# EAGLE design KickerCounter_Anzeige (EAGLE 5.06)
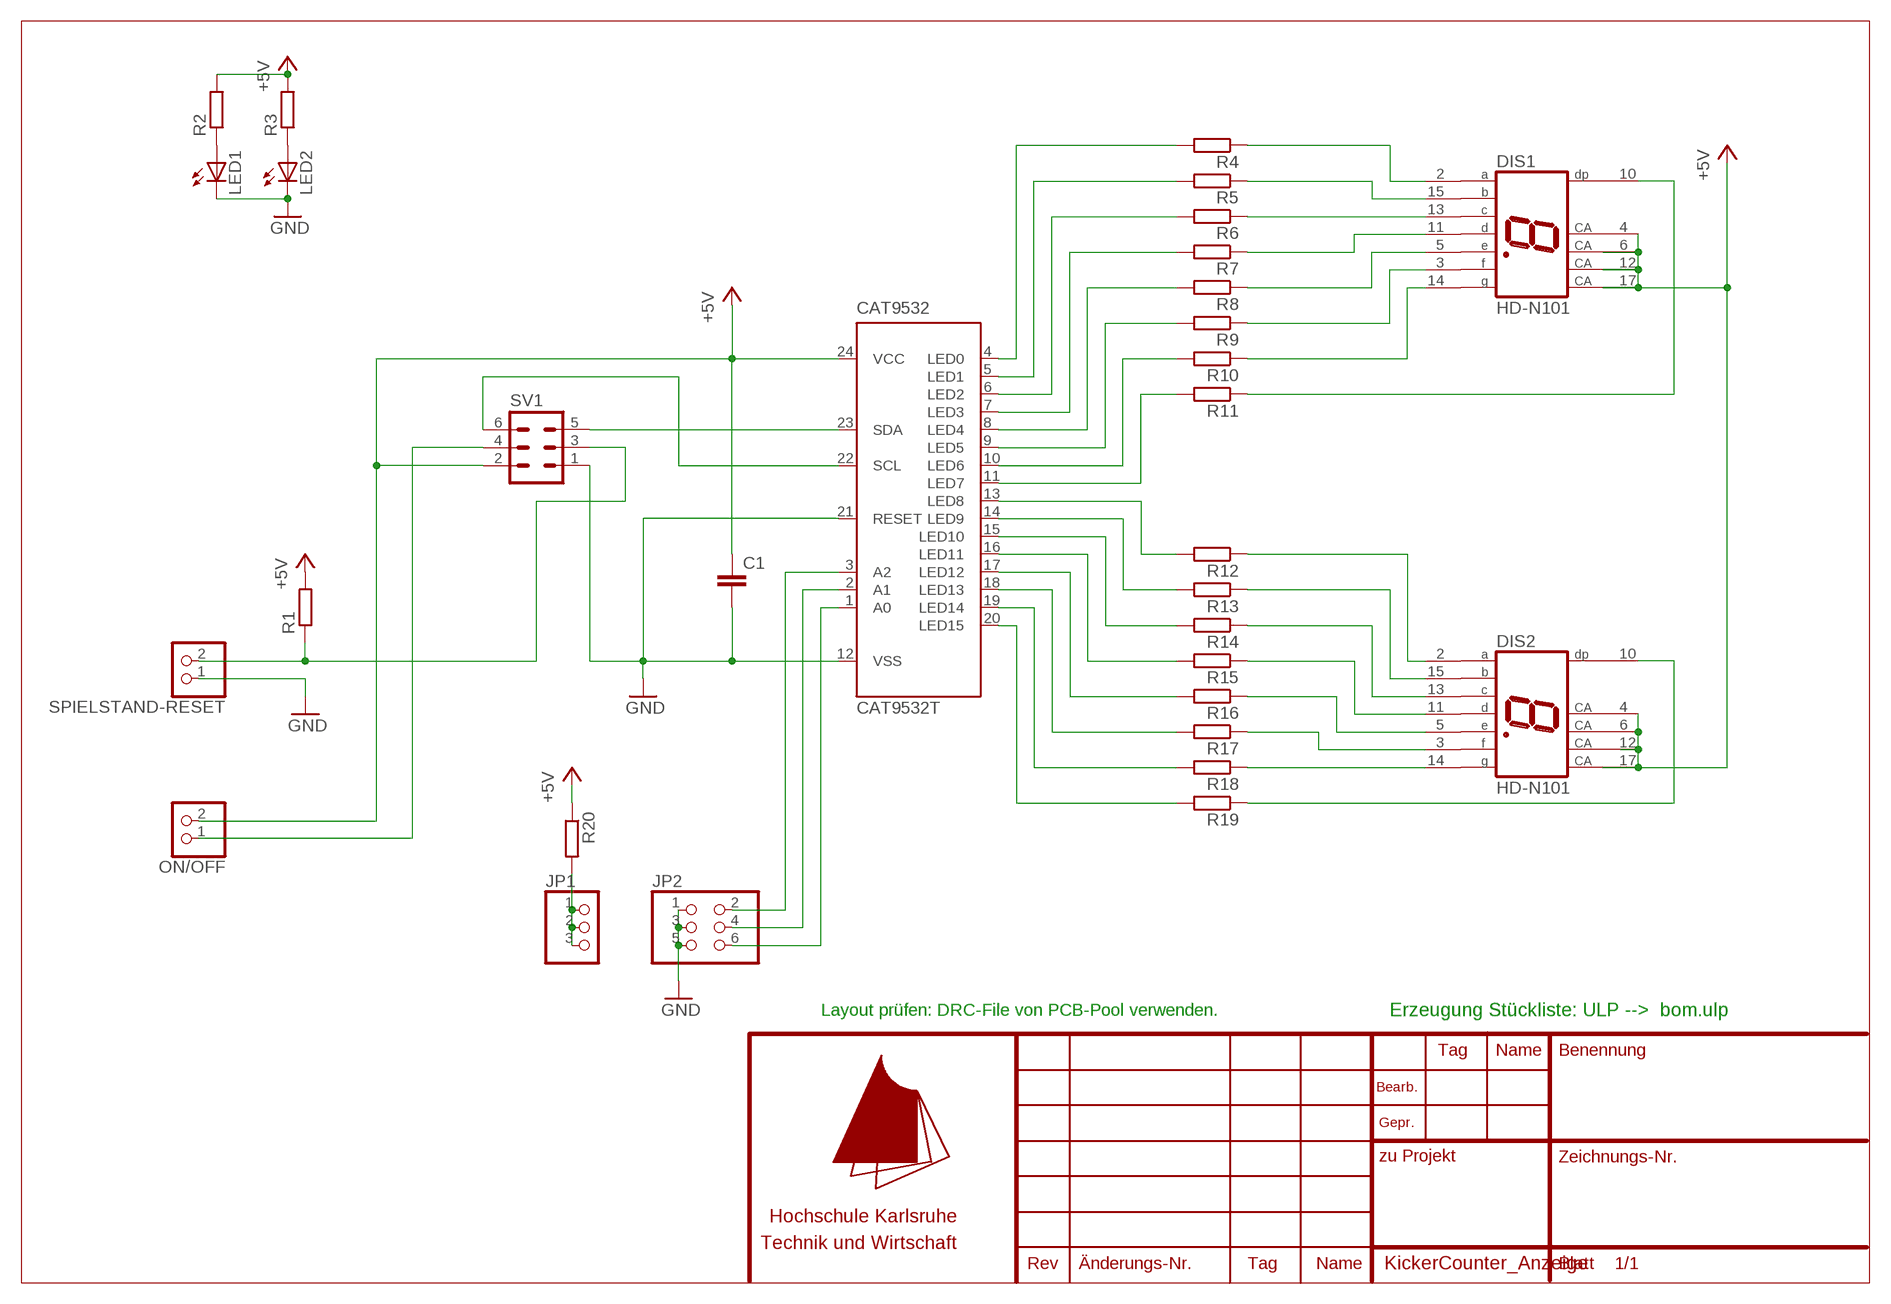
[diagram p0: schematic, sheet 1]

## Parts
C1  C-EUC1206  [C1206]
DIS1  HD-N101  [HDSP-Q]
DIS2  HD-N101  [HDSP-Q]
IC1  CAT9532T  [SO24]
JP1  PINHD-1X3  [1X03]
JP2  PINHD-2X3  [2X03]
LED1  LED3MM  [LED3MM]
LED2  LED3MM  [LED3MM]
ON/OFF  PINHD-1X2  [1X02]
R1  R-EU_R1206  [R1206]
R2  R-EU_R1206  [R1206]
R3  R-EU_R1206  [R1206]
R4  R-EU_R1206  [R1206]
R5  R-EU_R1206  [R1206]
R6  R-EU_R1206  [R1206]
R7  R-EU_R1206  [R1206]
R8  R-EU_R1206  [R1206]
R9  R-EU_R1206  [R1206]
R10  R-EU_R1206  [R1206]
R11  R-EU_R1206  [R1206]
R12  R-EU_R1206  [R1206]
R13  R-EU_R1206  [R1206]
R14  R-EU_R1206  [R1206]
R15  R-EU_R1206  [R1206]
R16  R-EU_R1206  [R1206]
R17  R-EU_R1206  [R1206]
R18  R-EU_R1206  [R1206]
R19  R-EU_R1206  [R1206]
R20  R-EU_R1206  [R1206]
SPIELSTAND-RESET  PINHD-1X2  [1X02]
SV1  ML6  [ML6]

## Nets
+5V: C1.1 DIS1.4(CA) DIS1.6(CA) DIS1.12(CA) DIS1.17(CA) DIS2.4(CA) DIS2.6(CA) DIS2.12(CA) DIS2.17(CA) IC1.24(VCC) ON/OFF.2 R1.2 R2.2 R3.2 R20.1 SV1.2
GND: C1.2 IC1.12(VSS) IC1.21(RESET) JP2.1 JP2.3 JP2.5 LED1.K(C) LED2.K(C) SPIELSTAND-RESET.1 SV1.1
N$1: IC1.1(A0) JP2.6
N$2: IC1.2(A1) JP2.4
N$3: IC1.3(A2) JP2.2
N$4: IC1.4(LED0) R4.2
N$5: IC1.5(LED1) R5.2
N$6: IC1.6(LED2) R6.2
N$7: IC1.7(LED3) R7.2
N$8: IC1.8(LED4) R8.2
N$9: IC1.9(LED5) R9.2
N$10: IC1.10(LED6) R10.2
N$11: IC1.11(LED7) R11.2
N$12: DIS1.2(A) R4.1
N$13: DIS1.15(B) R5.1
N$14: DIS1.3(F) R9.1
N$15: DIS1.14(G) R10.1
N$16: DIS1.5(E) R8.1
N$17: DIS1.11(D) R7.1
N$18: DIS1.13(C) R6.1
N$19: DIS1.10(DP) R11.1
N$20: LED1.A R2.1
N$21: IC1.23(SDA) SV1.5
N$22: IC1.22(SCL) SV1.6
N$23: LED2.A R3.1
N$24: ON/OFF.1 SV1.4
N$25: R1.1 SPIELSTAND-RESET.2 SV1.3
N$26: IC1.13(LED8) R12.2
N$27: IC1.14(LED9) R13.2
N$28: IC1.15(LED10) R14.2
N$29: IC1.16(LED11) R15.2
N$30: IC1.17(LED12) R16.2
N$31: IC1.18(LED13) R17.2
N$32: IC1.19(LED14) R18.2
N$33: IC1.20(LED15) R19.2
N$34: DIS2.2(A) R12.1
N$35: DIS2.15(B) R13.1
N$36: DIS2.13(C) R14.1
N$37: DIS2.11(D) R15.1
N$38: DIS2.5(E) R16.1
N$39: DIS2.3(F) R17.1
N$40: DIS2.14(G) R18.1
N$41: DIS2.10(DP) R19.1
N$42: JP1.1 JP1.2 JP1.3 R20.2

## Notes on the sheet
- Layout prüfen: DRC-File von PCB-Pool verwenden. | Erzeugung Stückliste: ULP -->  bom.ulp

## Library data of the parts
C1 = rcl:C-EU: CAPACITOR, European symbol
DIS1 DIS2 = display-hp:HD-N101: LED DISPLAY 1-character 7 segment, decimal point right
IC1 = CAT9532:CAT9532: I2C-Bus 4-digit LED-DRIVER
JP1 = pinhead:PINHD-1X3: PIN HEADER
JP2 = pinhead:PINHD-2X3: PIN HEADER
LED1 LED2 = led:LED: LED
ON/OFF SPIELSTAND-RESET = pinhead:PINHD-1X2: PIN HEADER
R1-R20 = rcl:R-EU_: RESISTOR, European symbol
SV1 = con-ml:ML6: HARTING

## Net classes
0 default: width 0.152 mm, drill 0.305 mm, clearance 0.4 mm
1 5V: width 0.305 mm, drill 0.305 mm, clearance 0.4 mm
2 3V3: width 0.305 mm, drill 0.305 mm, clearance 0.4 mm

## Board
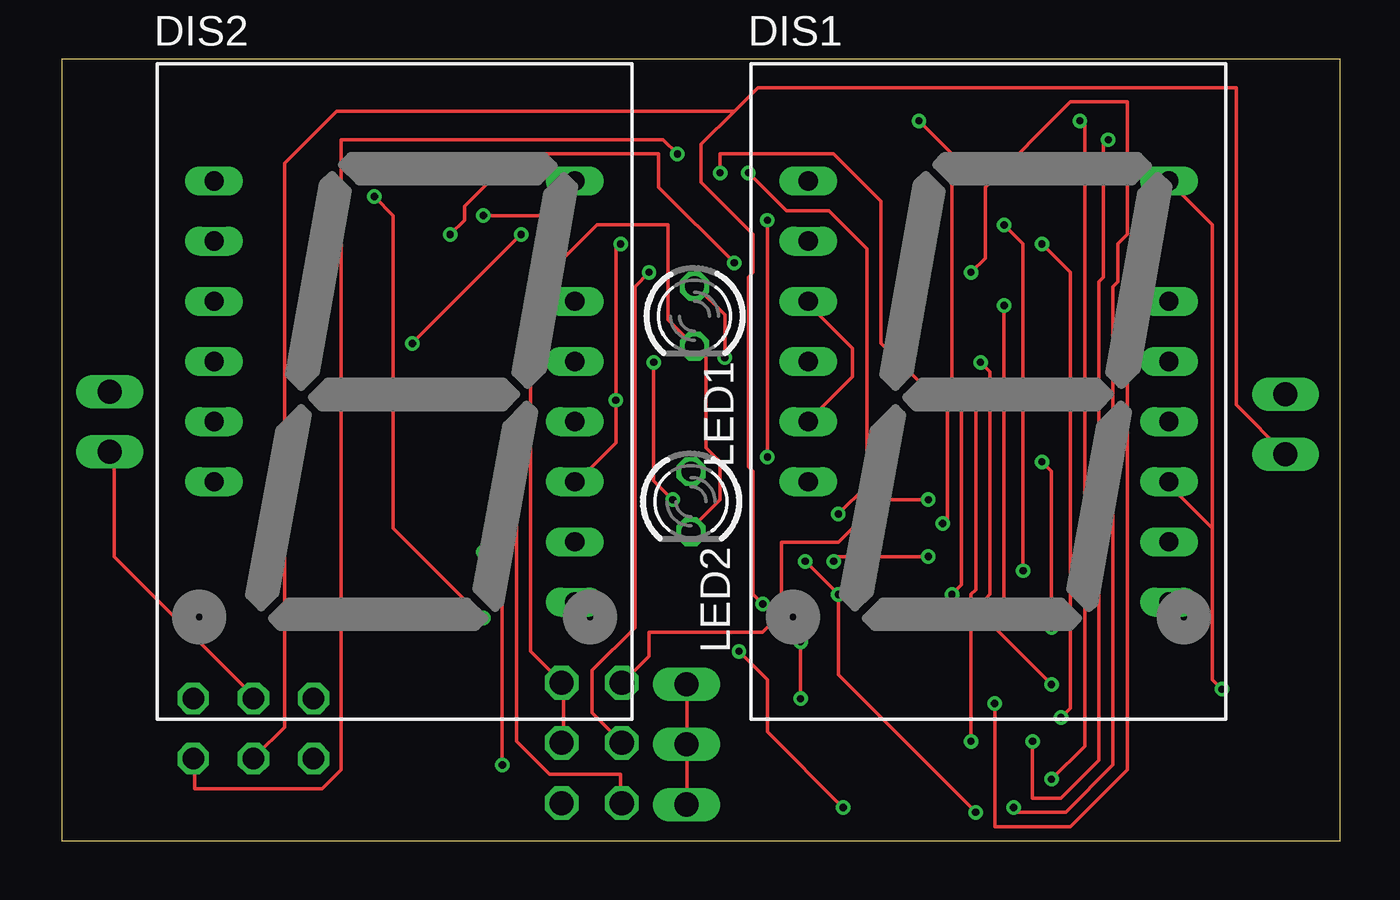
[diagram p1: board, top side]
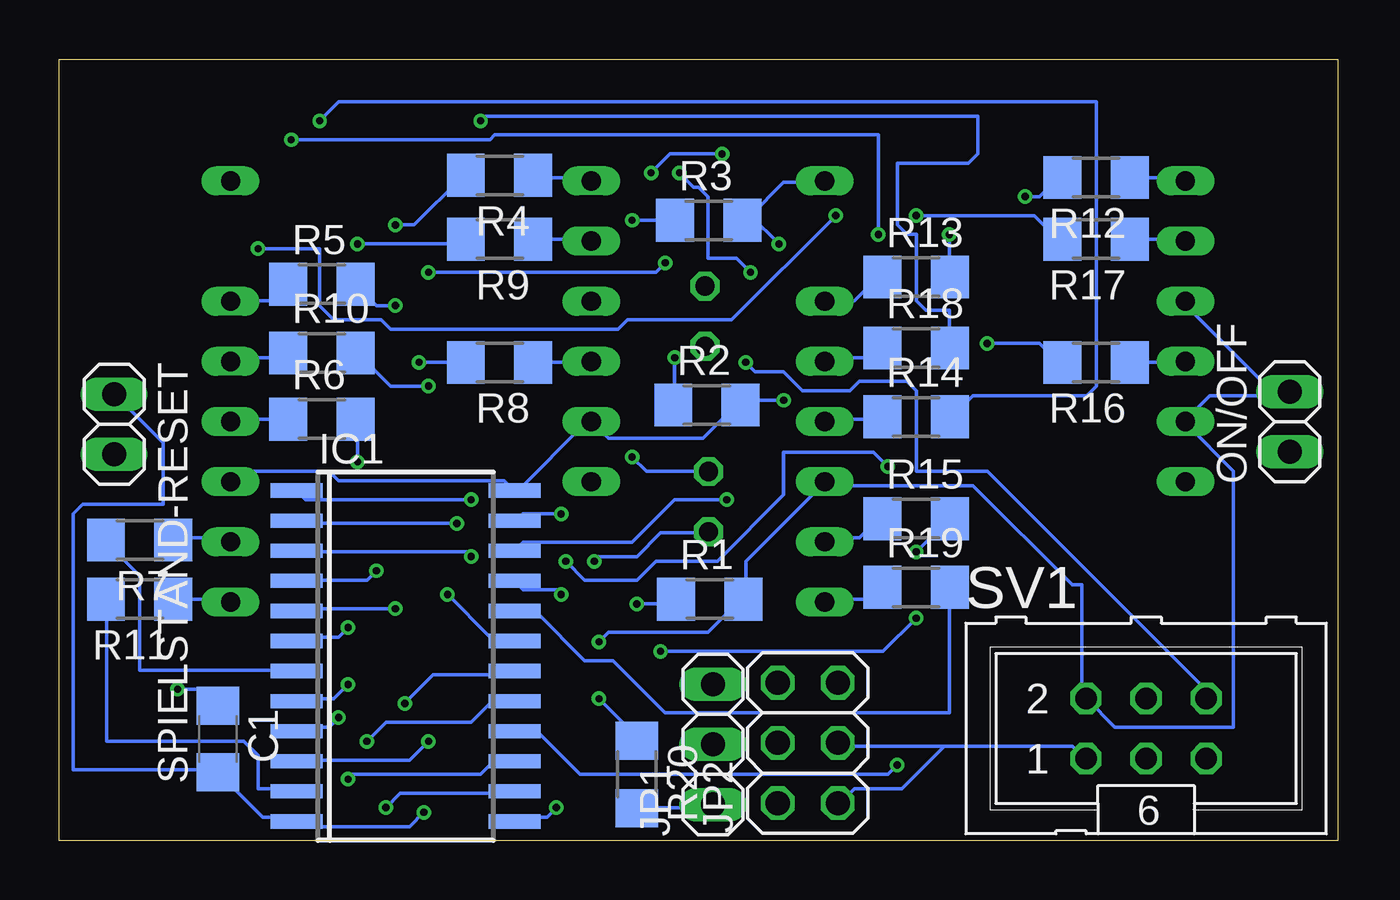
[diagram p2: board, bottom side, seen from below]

Size 54 x 33 mm. Coordinates in mm from the lower left corner, seen from the top.
Outline: 0,0 54,0 54,33 0,33 0,0
Copper layers (1*16): Top 0.035mm / dielectric 1.5mm / Bottom 0.035mm
Design rules "PCB-POOL": minimum track width 6mil, minimum drill 12mil, track to track 6mil, track to pad 6mil, pad to pad 6mil, via to via 6mil, smd to smd 6mil, copper to edge 20mil, drill to drill 8mil, minimum pad ring 8mil, minimum via ring 6mil, stop-mask expansion 3mil, vias tented up to drill 0mil, thermal gap 8mil

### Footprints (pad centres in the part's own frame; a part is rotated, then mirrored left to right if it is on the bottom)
C1206 = smd 1.6 x 1.8: 1 -1.4,0; 2 1.4,0
HDSP-Q = drill 0.813 long: 2 -7.62,8.89; 3 -7.62,6.35; 4 -7.62,3.81; 5 -7.62,1.27; 6 -7.62,-1.27; 7 -7.62,-3.81; 10 7.62,-8.89; 11 7.62,-6.35; 12 7.62,-3.81; 13 7.62,-1.27; 14 7.62,1.27; 15 7.62,3.81; 17 7.62,8.89
SO24 = smd 0.6 x 2.2: 1 -6.985,-4.6; 2 -5.715,-4.6; 3 -4.445,-4.6; 4 -3.175,-4.6; 5 -1.905,-4.6; 6 -0.635,-4.6; 7 0.635,-4.6; 8 1.905,-4.6; 9 3.175,-4.6; 10 4.445,-4.6; 11 5.715,-4.6; 12 6.985,-4.6; 13 6.985,4.6; 14 5.715,4.6; 15 4.445,4.6; 16 3.175,4.6; 17 1.905,4.6; 18 0.635,4.6; 19 -0.635,4.6; 20 -1.905,4.6; 21 -3.175,4.6; 22 -4.445,4.6; 23 -5.715,4.6; 24 -6.985,4.6
1X03 = drill 1.016 long: 1 -2.54,0; 2 0,0; 3 2.54,0
2X03 = drill 1.016 octagon: 1 -2.54,-1.27; 2 -2.54,1.27; 3 0,-1.27; 4 0,1.27; 5 2.54,-1.27; 6 2.54,1.27
LED3MM = drill 0.813 octagon: A -1.27,0; K 1.27,0
1X02 = drill 1.016 long: 1 -1.27,0; 2 1.27,0
R1206 = smd 1.6 x 1.803: 1 -1.422,0; 2 1.422,0
ML6 = drill 0.914 octagon: 1 -2.54,-1.27; 2 -2.54,1.27; 3 0,-1.27; 4 0,1.27; 5 2.54,-1.27; 6 2.54,1.27

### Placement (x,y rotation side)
C1  47.3,4.3 270 bottom
DIS1  39.14,18.97 0 top
DIS2  14.05,18.97 0 top
IC1  39.37,7.8 270 bottom
JP1  26.38,4.07 90 bottom
JP2  22.38,4.13 90 bottom
LED1  26.72,22.15 270 top
LED2  26.57,14.32 270 top
ON/OFF  2.02,17.69 90 bottom
R1  26.52,10.2 0 bottom
R2  26.64,18.4 0 bottom
R3  26.56,26.2 0 bottom
R4  35.4,28.1 180 bottom
R5  42.9,23.5 0 bottom
R6  42.9,17.8 0 bottom
R7  50.6,12.7 180 bottom
R8  35.4,20.2 180 bottom
R9  35.4,25.4 180 bottom
R10  42.9,20.6 0 bottom
R11  50.6,10.2 180 bottom
R12  10.2,28 180 bottom
R13  17.8,23.8 0 bottom
R14  17.8,17.9 0 bottom
R15  17.8,13.6 0 bottom
R16  10.2,20.2 180 bottom
R17  10.2,25.4 180 bottom
R18  17.8,20.8 0 bottom
R19  17.8,10.7 0 bottom
R20  29.6,2.8 270 bottom
SPIELSTAND-RESET  51.68,17.59 270 bottom
SV1  8.09,4.74 0 bottom

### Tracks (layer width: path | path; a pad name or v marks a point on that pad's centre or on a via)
+5V  (via drill 0.3)
  Top 0.152: DIS1.4 31.6,22.6 33.4,20.8 33.4,19.6 31.6,17.8 DIS1.6 | v49,6.4 48.6,6.8 48.6,13.2 | 48.6,13.2 46.8,15 DIS1.12 | 48.6,13.2 48.6,26 46.8,27.8 DIS1.17 | v31.2,8.4 v31.2,6 | v23.6,25.2 23.4,25 v23.4,18.6 23.4,16.8 21.8,15.2 DIS2.12
  Bottom 0.152: v49,6.4 48,6.4 C1.1 | DIS1.12 46.6,15.2 46.2,15.6 42.6,15.6 42.2,15.2 35.2,15.2 34.8,14.8 IC1.24 34.6,14.8 31.8,17.6 31.6,17.6 DIS1.6 31.4,17.6 30.8,17 26.8,17 25.4,18.4 R2.2 25.2,18.4 25,18.6 v23.4,18.6 | 2.6,18.8 2.2,18.8 ON/OFF.2 2.6,18.8 | 2.6,18.8 5.4,18.8 6.4,17.8 DIS2.6 6.4,17.6 4.4,15.6 4.4,4.8 9.4,4.8 10.6,6 SV1.2 10.8,6.2 10.8,10.8 11.2,10.8 15.4,15 21.6,15 DIS2.12 21.8,15 25,11.8 25,10.2 R1.2 25.2,10.2 26.6,8.8 30.8,8.8 v31.2,8.4 | 2.6,18.8 6.4,22.6 DIS2.4 | 24.8,26.4 23.4,27.8 21.8,27.8 DIS2.17 | 24.8,26.4 25,26.2 R3.2 24.8,26.4 | v31.2,6 29.6,4.4 R20.1 | v23.6,25.2 24.8,26.4
GND  (via drill 0.3)
  Top 0.152: JP2.3 21.2,4.2 21.2,6.6 JP2.5 21,6.8 19.8,8 19.8,23.2 22.6,26 25.6,26 25.6,22 LED1.K 27.2,20.4 27.2,16.6 27.8,16 27.8,14.4 26.6,13.2 LED2.K | v31.4,11.8 v32.8,10.4 32.8,7 v38.6,1.2
  Bottom 0.152: SPIELSTAND-RESET.1 51.6,18.8 49.6,16.8 49.6,14.2 53,14.2 53.4,13.8 53.4,3 47.4,3 C1.2 45.4,1 44,1 IC1.12 43.8,0.8 43.6,0.6 39.2,0.6 v38.6,1.2 | 16.6,4 21,4 JP2.3 | 16.6,4 11.2,4 10.8,3.6 SV1.1 | 16.6,4 18.4,2.2 20.4,2.2 21,1.6 JP2.1 | v32.8,10.4 33,10.6 34.4,10.6 34.6,10.8 IC1.21 | v31.4,11.8 31.2,12 29.6,12 28.6,13 26.6,13 LED2.K
N$1  (via drill 0.3)
  Top 0.152: v36.6,14.4 34.2,14.4 34.2,14 32.8,12.6 30.4,12.6 30.4,9.6 29.6,8.8 24.8,8.8 24.8,7.8 23.8,6.8 JP2.6
  Bottom 0.152: v36.6,14.4 43.6,14.4 43.8,14.6 IC1.1
N$2  (via drill 0.3)
  Top 0.152: v37.2,13.4 37.4,13.6 37.4,18.2 34.6,21 34.6,27 32.6,29 27.8,29 v27.8,28.2 | v24.8,24 24.2,23.4 24.2,9 22.4,7.2 22.4,5.4 23.6,4.2 JP2.4
  Bottom 0.152: v37.2,13.4 43.8,13.4 IC1.2 | v27.8,28.2 27.2,27.6 27,27.6 26.6,27.2 26.6,24.6 25.4,24.6 v24.8,24
N$3  (via drill 0.3)
  Top 0.152: v36.6,12 32.6,12 v32.6,11.8 | v19,15.8 19.2,15.6 19.2,4.2 20.6,2.8 23.6,2.8 23.6,1.6 JP2.2
  Bottom 0.152: v36.6,12 36.8,12.2 43.8,12.2 IC1.3 | v32.6,11.8 31.8,11 29.6,11 28.8,11.8 26.2,11.8 23.4,14.6 23.4,16.4 19.6,16.4 v19,15.8
N$4  (via drill 0.3)
  Top 0.152: v39.8,26 40.6,25.2 v40.6,11.4
  Bottom 0.152: v39.8,26 39,26 37,28 R4.2 | v40.6,11.4 41,11 43.8,11 IC1.4
N$5  (via drill 0.3)
  Top 0.152: v39.8,9.8 v39.8,22.6
  Bottom 0.152: v39.8,22.6 40.6,22.6 41.4,23.4 R5.2 | v39.8,9.8 43.8,9.8 IC1.5
N$6  (via drill 0.3)
  Top 0.152: v41.4,16 41.8,15.6 v41.8,9
  Bottom 0.152: v41.4,16 41.4,17.8 R6.2 | v41.8,9 42.2,8.6 43.8,8.6 IC1.6
N$7
  Bottom 0.152: R7.2 52,12.6 50.6,11.2 50.6,7.2 44,7.2 IC1.7
N$8  (via drill 0.3)
  Top 0.152: v38.8,20.2 39.2,19.8 39.2,10.4 39,10.2 39,9.4 v41.8,6.6
  Bottom 0.152: v41.8,6.6 42.4,6 43.8,6 IC1.8 | v38.8,20.2 R8.2
N$9  (via drill 0.3)
  Top 0.152: v41.4,25.2 42.6,24 42.6,5.6 v42.2,5.2
  Bottom 0.152: v41.4,25.2 37.2,25.2 37,25.4 R9.2 | v42.2,5.2 42.6,4.8 43.8,4.8 IC1.9
N$10  (via drill 0.3)
  Top 0.152: v38.4,19.2 38.6,19 38.6,10.6 38.4,10.4 v38.4,4.2
  Bottom 0.152: v38.4,19.2 40,19.2 41.4,20.6 R10.2 | v38.4,4.2 39.2,3.4 43.8,3.4 IC1.10
N$11
  Bottom 0.152: R11.2 52,10.2 52,4.2 46.2,4.2 45.6,3.6 45.6,2.2 44,2.2 IC1.11
N$12
  Bottom 0.152: R4.1 33.8,28 31.6,28 DIS1.2
N$13
  Bottom 0.152: R5.1 44.4,23.4 45,22.8 46.6,22.8 DIS1.15
N$14
  Bottom 0.152: R9.1 31.6,25.4 DIS1.3
N$15
  Bottom 0.152: R10.1 44.4,20.6 44.6,20.4 46.6,20.4 DIS1.14
N$16
  Bottom 0.152: R8.1 31.6,20.2 DIS1.5
N$17
  Bottom 0.152: R7.1 49,12.8 46.8,12.8 DIS1.11
N$18
  Bottom 0.152: R6.1 46.6,17.8 DIS1.13
N$19
  Bottom 0.152: R11.1 46.8,10.2 DIS1.10
N$20  (via drill 0.3)
  Top 0.152: v28,20.4 28,22.2 26.8,23.4 LED1.A
  Bottom 0.152: v28,20.4 28,18.4 R2.1
N$21  (via drill 0.3)
  Top 0.152: v32.8,13.8 34,15 34,25 32.4,26.6 30.6,26.6 v29,28.2 | v26,29 25.4,29.6 11.8,29.6 11.8,3 11,2.2 5.6,2.2 5.6,3.4 SV1.5
  Bottom 0.152: v32.8,13.8 34.4,13.8 34.6,13.6 IC1.23 | v29,28.2 28.2,29 v26,29
N$22  (via drill 0.3)
  Top 0.152: v25.8,14.4 25,15.2 v25,20.2
  Bottom 0.152: v25.8,14.4 28,14.4 29.8,12.6 34.4,12.6 34.6,12.4 IC1.22 | v25,20.2 24.6,19.8 23.4,19.8 22.6,19 20.6,19 20.2,19.4 18.2,19.4 17.8,19 17.8,15.6 14.8,15.6 5.4,6.2 SV1.6
N$23  (via drill 0.3)
  Top 0.152: v29.8,16.2 v29.8,26.2
  Bottom 0.152: v29.8,16.2 29.2,15.6 26.6,15.6 LED2.A | v29.8,26.2 R3.1
N$24
  Top 0.152: SV1.4 8,6.2 2.2,12 2.2,16.4 ON/OFF.1
N$25  (via drill 0.3)
  Top 0.152: v29.6,10 29.2,10.4 29.2,15.6 29,15.8 29,23.8 29.2,24 29.2,25.6 27,27.8 27,29.4 28.4,30.8 | 28.4,30.8 29.4,31.8 49.6,31.8 49.6,18.4 SPIELSTAND-RESET.2 | 28.4,30.8 11.6,30.8 9.4,28.6 9.4,4.8 8.2,3.6 SV1.3
  Bottom 0.152: v29.6,10 28.2,10 28,10.2 R1.1
N$26  (via drill 0.3)
  Top 0.152: v13.2,27.2 14,26.4 14,13.2 v17.8,9.4 | v28.6,8 29.8,6.8 29.8,4.6 v33,1.4
  Bottom 0.152: v13.2,27.2 12.6,27.2 11.8,28 R12.2 | v17.8,9.4 19.2,8 v28.6,8 | v33,1.4 33.4,1 34.6,1 IC1.13
N$27  (via drill 0.3)
  Top 0.152: v16.4,25.6 17,26.2 17,26.8 19.2,29 25.2,29 25.2,27.6 v28.4,24.4 | v38.4,24 39,24.6 39,27.6 42.6,31.2 45,31.2 45,25.6 44.6,25.2 44.6,23.6 44.4,23.4 44.4,3.2 42.4,1.2 40.2,1.2 v40.2,1.4
  Bottom 0.152: v16.4,25.6 16.4,23.8 R13.2 | v28.4,24.4 28.8,24 v38.4,24 | v40.2,1.4 39.6,2 34.8,2 IC1.14
N$28  (via drill 0.3)
  Top 0.152: v43,30.4 43.2,30.2 43.2,4 v41.8,2.6
  Bottom 0.152: v43,30.4 42.2,31.2 10.2,31.2 10.2,19.2 10.6,18.8 15.4,18.8 16.2,18 R14.2 | v41.8,2.6 41.6,2.8 36.2,2.8 35.8,3.2 34.8,3.2 IC1.15
N$29  (via drill 0.3)
  Top 0.152: v17.8,12.2 18.6,11.4 v18.6,3.2
  Bottom 0.152: v17.8,12.2 16.4,13.6 R15.2 | v18.6,3.2 19,2.8 32,2.8 33.8,4.6 34.6,4.6 IC1.16
N$30  (via drill 0.3)
  Top 0.152: v14.8,21 v19.4,25.6 | v44.2,29.6 44,29.4 44,23.8 43.8,23.6 43.8,3.4 42.2,1.8 41,1.8 v41,4.2
  Bottom 0.152: v14.8,21 12.6,21 11.8,20.2 R16.2 | v19.4,25.6 19.4,29.8 35.6,29.8 35.8,29.6 v44.2,29.6 | v41,4.2 40.2,5 36.6,5 35.8,5.8 34.8,5.8 IC1.17
N$31  (via drill 0.3)
  Top 0.152: v17.8,26.4 v21.2,26.4 | v45.6,25 45.2,24.6 45.2,23.4 45,23.2 45,3 42.6,0.6 39.4,0.6 v39.4,5.8
  Bottom 0.152: v17.8,26.4 12.8,26.4 11.8,25.4 R17.2 | v21.2,26.4 25.6,22 30,22 30.4,21.6 40,21.6 40.4,22 42.4,22 43,22.6 43,25 v45.6,25 | v39.4,5.8 38.2,7 34.8,7 IC1.18
N$32  (via drill 0.3)
  Top 0.152: v36.2,30.4 37.6,29 37.6,18.8 38,18.4 38,10.8 v37.6,10.4
  Bottom 0.152: v36.2,30.4 36,30.6 15.2,30.6 15.2,29 15.6,28.6 18.6,28.6 18.6,26 18.2,25.6 17.8,25.6 17.8,22.8 17.4,22.4 16.4,22.4 16.4,20.8 R18.2 | v37.6,10.4 35.8,8.6 34.8,8.6 IC1.19
N$33
  Bottom 0.152: R19.2 16.4,10.6 16.4,5.4 28.4,5.4 30.6,7.6 31.8,7.6 33.8,9.6 34.6,9.6 IC1.20
N$34
  Bottom 0.152: R12.1 6.6,28 DIS2.2
N$35
  Bottom 0.152: R13.1 19.4,23.8 20.4,22.8 21.6,22.8 DIS2.15
N$36
  Bottom 0.152: R14.1 19.4,17.8 21.6,17.8 DIS2.13
N$37
  Bottom 0.152: R15.1 19.4,13.6 20.2,12.8 21.6,12.8 DIS2.11
N$38
  Bottom 0.152: R16.1 6.6,20.2 DIS2.5
N$39
  Bottom 0.152: R17.1 6.6,25.4 DIS2.3
N$40
  Bottom 0.152: R18.1 19.4,20.8 19.8,20.4 21.6,20.4 DIS2.14
N$41
  Bottom 0.152: R19.1 19.4,10.6 19.8,10.2 21.6,10.2 DIS2.10
N$42
  Top 0.152: JP1.3 26.4,6.6 26.4,4.2 JP1.2 26.4,4 26.4,1.6 JP1.1
  Bottom 0.152: R20.2 29.6,1.4 26.4,1.4 JP1.1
